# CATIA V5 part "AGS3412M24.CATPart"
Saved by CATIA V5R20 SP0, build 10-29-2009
Part number: AGS3412M24
Definition: NONE
Nomenclature: AGS3412M24
Source: Unknown
Description: AGS3412M24
Bounding box of the stored display mesh (mm): x -33 to 35, y -32.5 to 32.5, z -32.5 to 32.5
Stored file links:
  C:\Users\Utente\Desktop\IO LAVORO\3D X SITO CF\X SITO\PLASTICA\AGS\AGS3412M24.CATPart
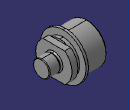
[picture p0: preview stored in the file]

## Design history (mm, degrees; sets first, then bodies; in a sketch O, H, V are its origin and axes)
Body1 "AGS3412M24" (main body)
  Solid1: solid without history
